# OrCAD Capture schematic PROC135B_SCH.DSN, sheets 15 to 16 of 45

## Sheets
15 15. SOC POWER: size C; title: SOC SUPPLY RAILS AND POWER SUPPLIES
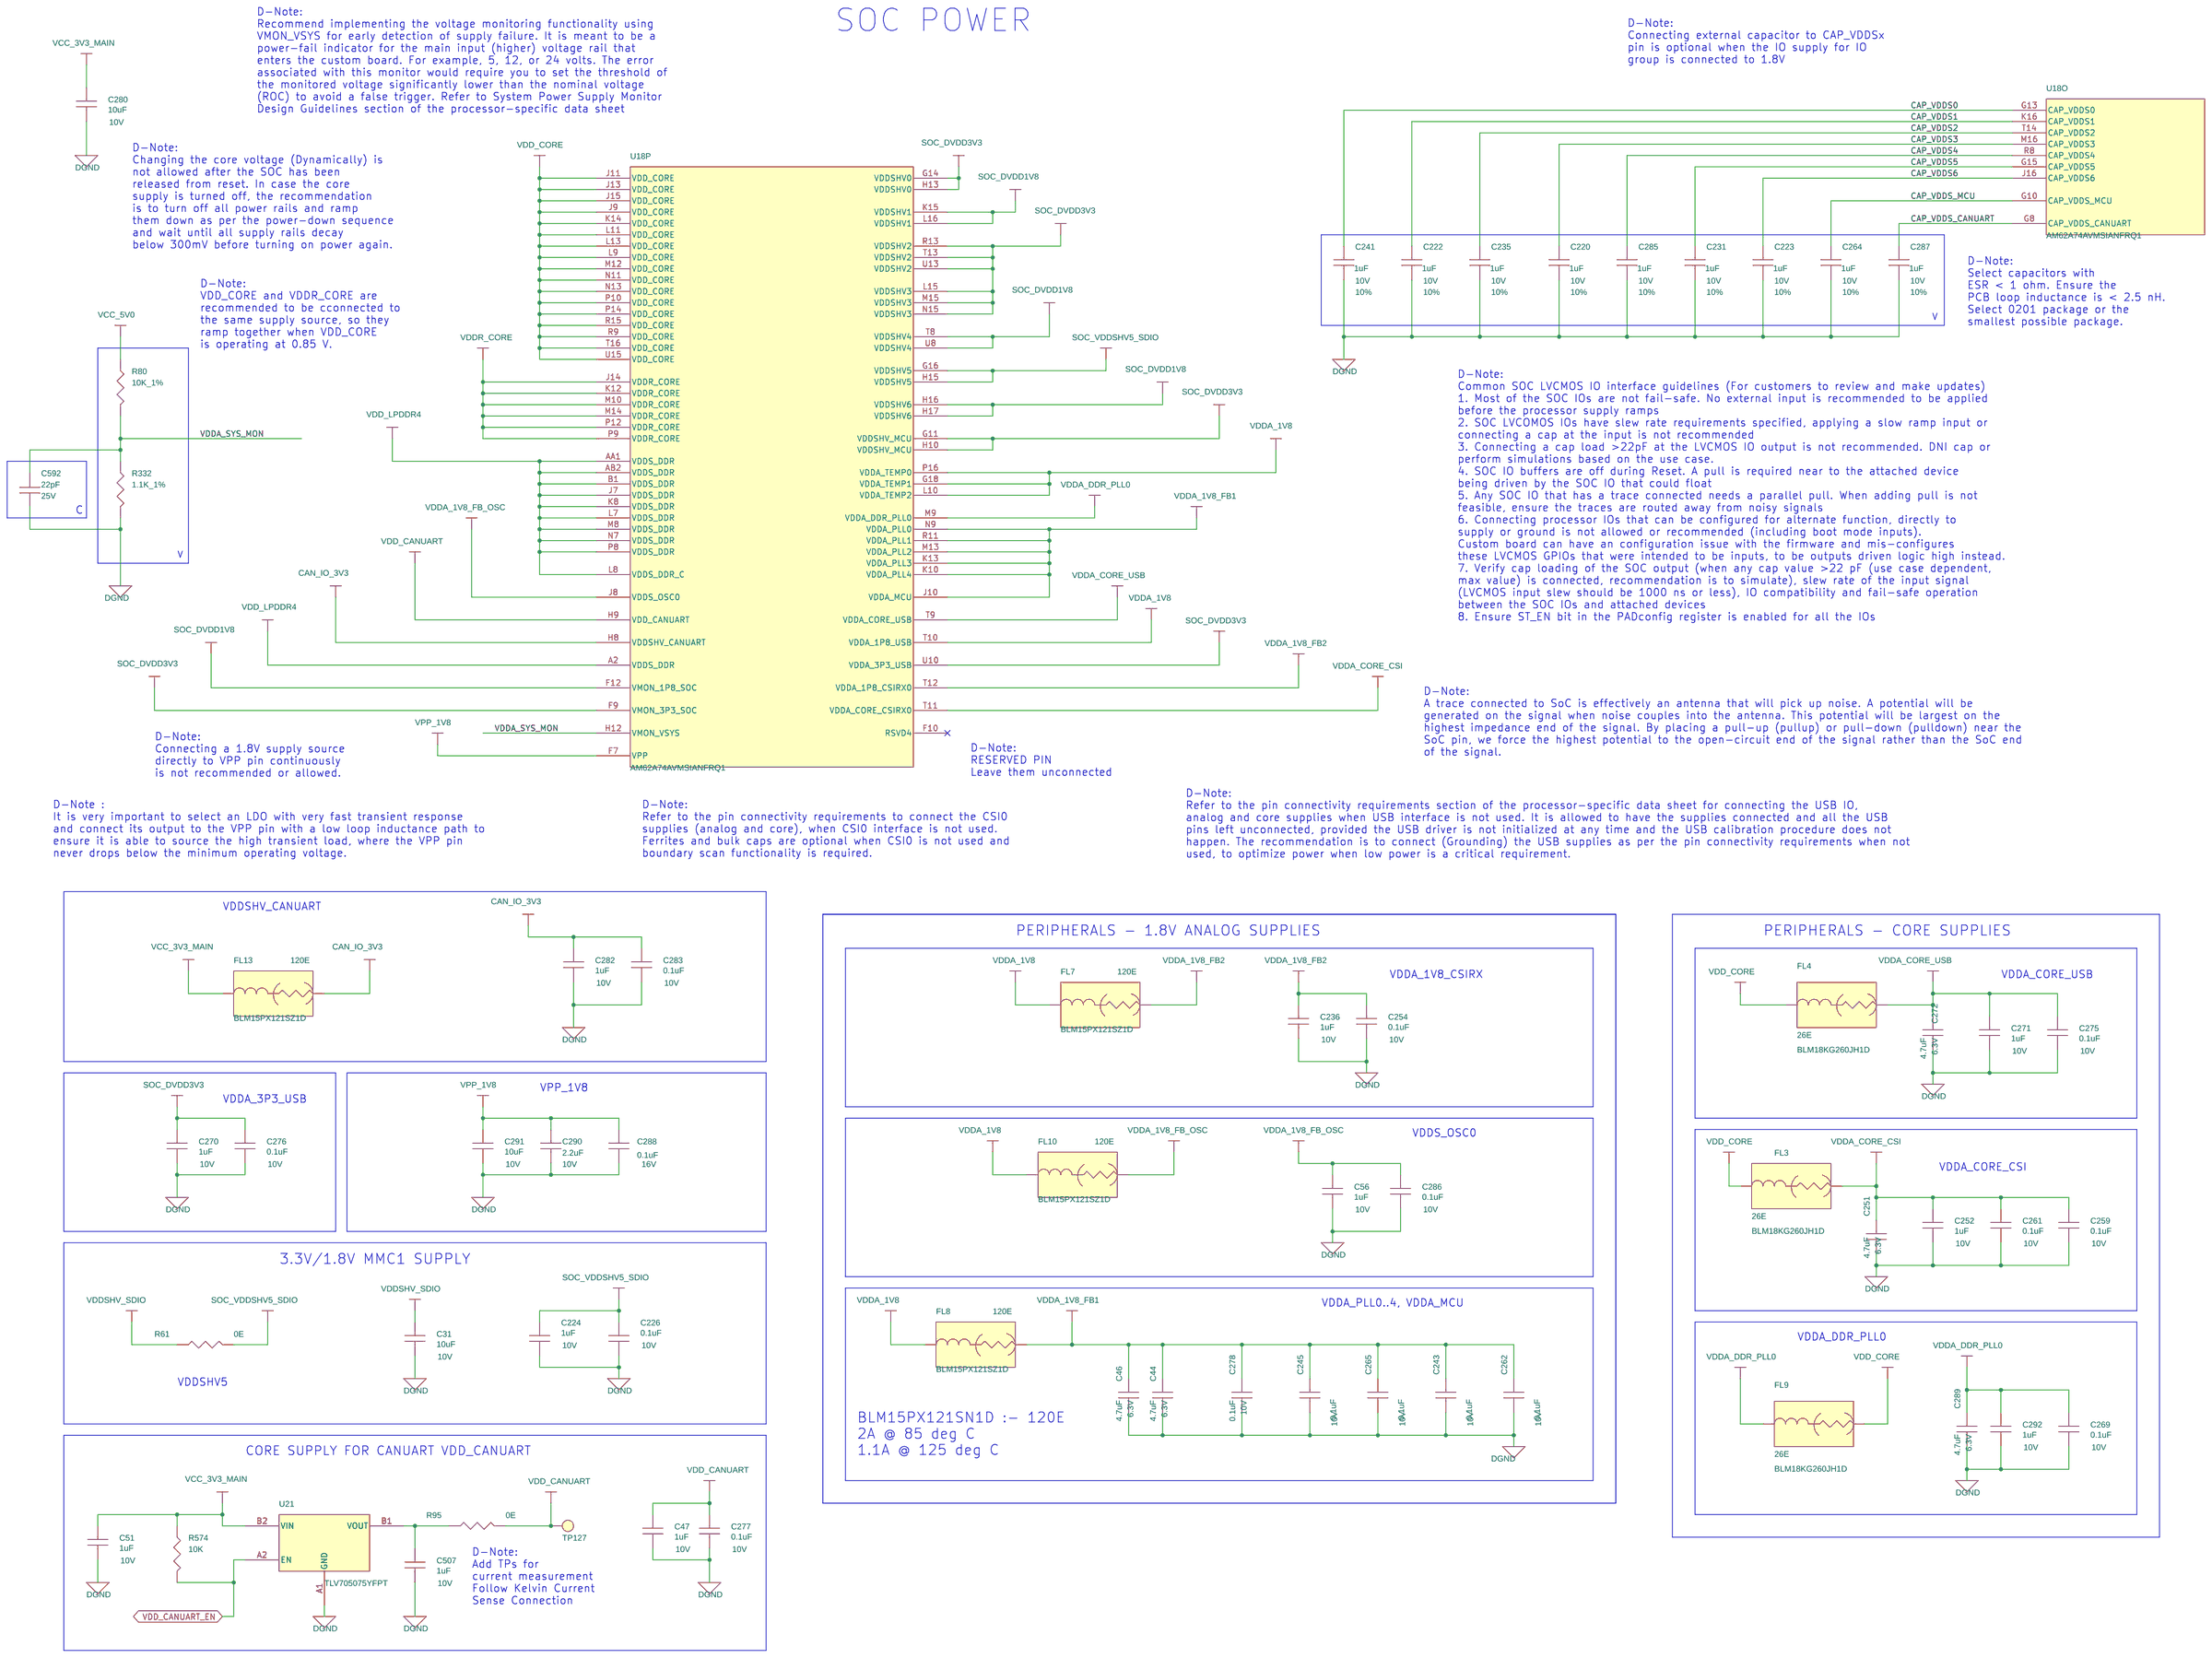
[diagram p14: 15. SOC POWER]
16 16. SOC POWER CAPS: size C; title: SOC POWER SUPPLIES - DECAPS & SOC GROUND VSS
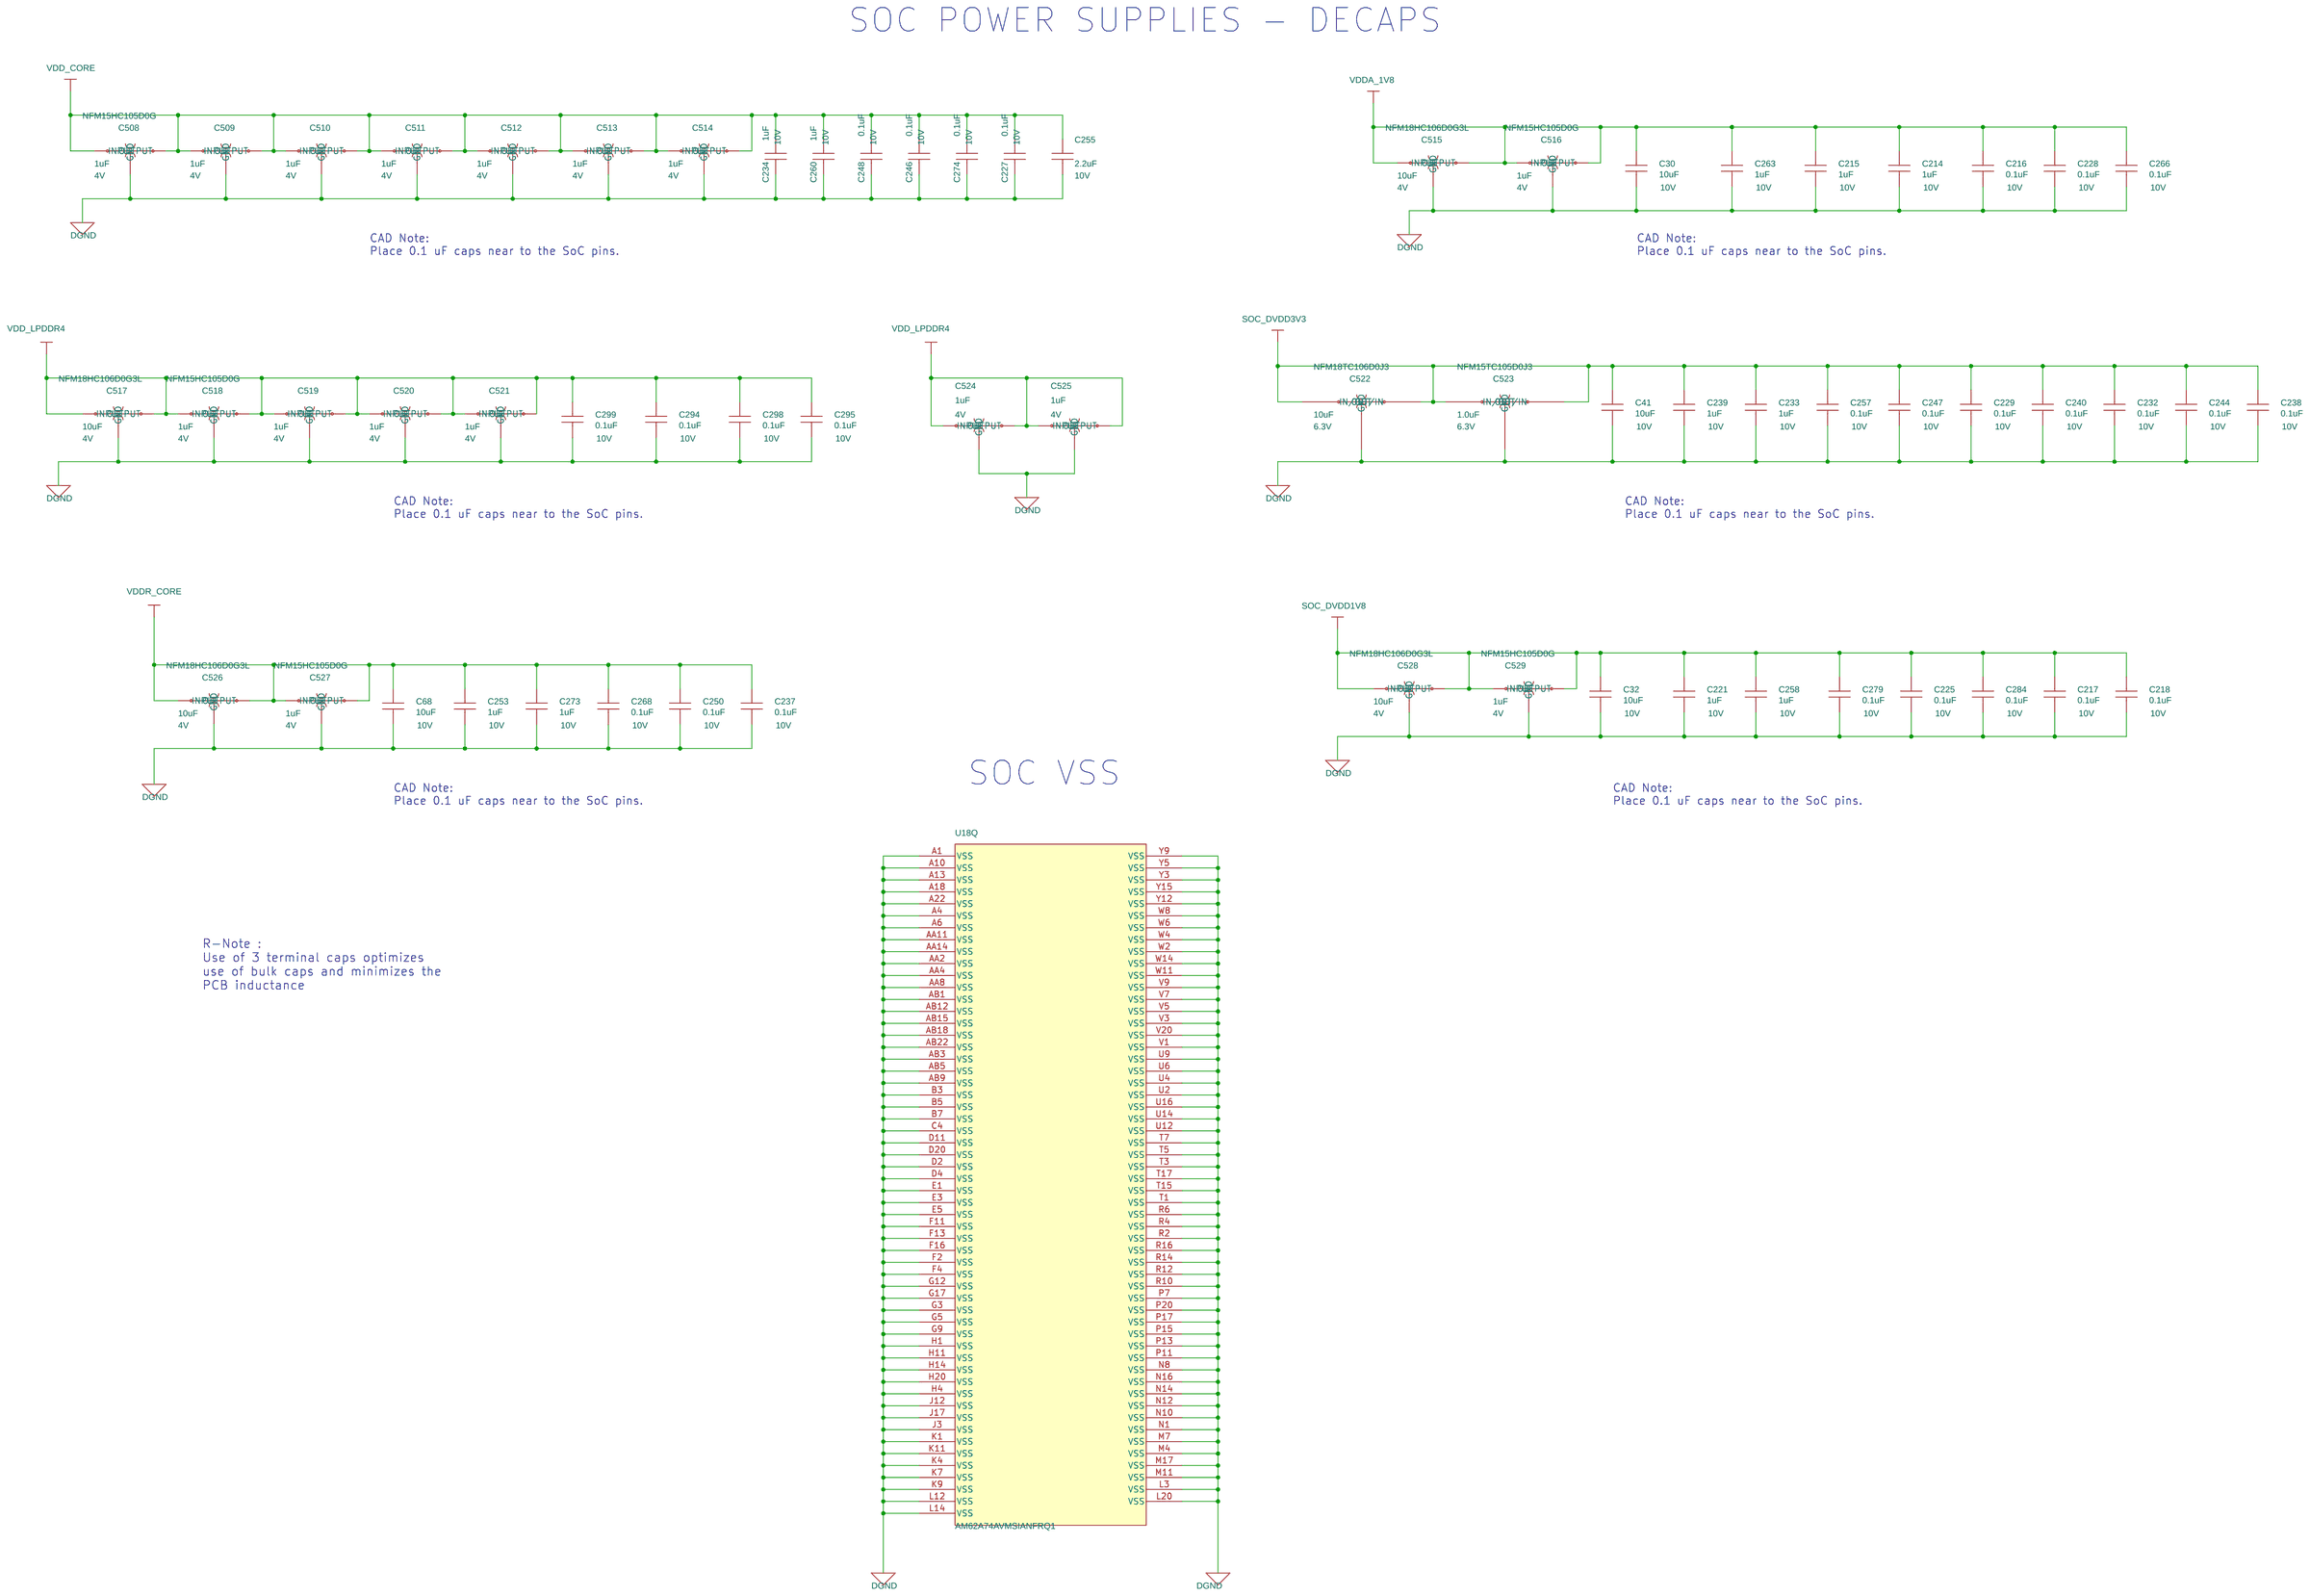
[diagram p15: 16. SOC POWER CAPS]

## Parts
sheet 15. SOC POWER
C31  10uF  [CAP0402_1]
C44  4.7uF  [CAP0201_0-5]
C46  4.7uF  [CAP0201_0-5]
C47  1uF  [CAP0201_0-5]
C51  1uF  [CAP0201_0-5]
C56  1uF  [CAP0201_0-5]
C220  1uF  [CAP0201_0-5]
C222  1uF  [CAP0201_0-5]
C223  1uF  [CAP0201_0-5]
C224  1uF  [CAP0201_0-5]
C226  0.1uF  [CAP0201_0-5]
C231  1uF  [CAP0201_0-5]
C235  1uF  [CAP0201_0-5]
C236  1uF  [CAP0201_0-5]
C241  1uF  [CAP0201_0-5]
C243  0.1uF  [CAP0201_0-5]
C245  0.1uF  [CAP0201_0-5]
C251  4.7uF  [CAP0201_0-5]
C252  1uF  [CAP0201_0-5]
C254  0.1uF  [CAP0201_0-5]
C259  0.1uF  [CAP0201_0-5]
C261  0.1uF  [CAP0201_0-5]
C262  0.1uF  [CAP0201_0-5]
C264  1uF  [CAP0201_0-5]
C265  0.1uF  [CAP0201_0-5]
C269  0.1uF  [CAP0201_0-5]
C270  1uF  [CAP0201_0-5]
C271  1uF  [CAP0201_0-5]
C272  4.7uF  [CAP0201_0-5]
C275  0.1uF  [CAP0201_0-5]
C276  0.1uF  [CAP0201_0-5]
C277  0.1uF  [CAP0201_0-5]
C278  0.1uF  [CAP0201_0-5]
C280  10uF  [CAP0402_1]
C282  1uF  [CAP0201_0-5]
C283  0.1uF  [CAP0201_0-5]
C285  1uF  [CAP0201_0-5]
C286  0.1uF  [CAP0201_0-5]
C287  1uF  [CAP0201_0-5]
C288  0.1uF  [CAP0201_0-5]
C289  4.7uF  [CAP0201_0-5]
C290  2.2uF  [CAP0201_0-75]
C291  10uF  [CAP0402_1]
C292  1uF  [CAP0201_0-5]
C507  1uF  [CAP0201_0-5]
C592  22pF  [CAP0201_0-5]
FL3  26E  [EMIFIL_BLM18P_0603_0-8]
FL4  26E  [EMIFIL_BLM18P_0603_0-8]
FL7  120E  [EMIFIL_BLM15A_0402_0-6]
FL8  120E  [EMIFIL_BLM15A_0402_0-6]
FL9  26E  [EMIFIL_BLM18P_0603_0-8]
FL10  120E  [EMIFIL_BLM15A_0402_0-6]
FL13  120E  [EMIFIL_BLM15A_0402_0-6]
R61  0E  [RES0402_0-5]
R80  10K_1%  [RES0402_0-5]
R95  0E  [RES0402_0-5]
R332  1.1K_1%  [RES0402_0-5]
R574  10K  [RES0201_0-5]
TP127  TP20_SMD  [TP20_SMD]
U21  TLV705075YFPT  [DSBGA4_15-74_30X30_0-5]
sheet 16. SOC POWER CAPS
C30  10uF  [CAP0402_1]
C32  10uF  [CAP0402_1]
C41  10uF  [CAP0402_1]
C68  10uF  [CAP0402_1]
C214  1uF  [CAP0201_0-5]
C215  1uF  [CAP0201_0-5]
C216  0.1uF  [CAP0201_0-5]
C217  0.1uF  [CAP0201_0-5]
C218  0.1uF  [CAP0201_0-5]
C221  1uF  [CAP0201_0-5]
C225  0.1uF  [CAP0201_0-5]
C227  0.1uF  [CAP0201_0-5]
C228  0.1uF  [CAP0201_0-5]
C229  0.1uF  [CAP0201_0-5]
C232  0.1uF  [CAP0201_0-5]
C233  1uF  [CAP0201_0-5]
C234  1uF  [CAP0201_0-5]
C237  0.1uF  [CAP0201_0-5]
C238  0.1uF  [CAP0201_0-5]
C239  1uF  [CAP0201_0-5]
C240  0.1uF  [CAP0201_0-5]
C244  0.1uF  [CAP0201_0-5]
C246  0.1uF  [CAP0201_0-5]
C247  0.1uF  [CAP0201_0-5]
C248  0.1uF  [CAP0201_0-5]
C250  0.1uF  [CAP0201_0-5]
C253  1uF  [CAP0201_0-5]
C255  2.2uF  [CAP0201_0-75]
C257  0.1uF  [CAP0201_0-5]
C258  1uF  [CAP0201_0-5]
C260  1uF  [CAP0201_0-5]
C263  1uF  [CAP0201_0-5]
C266  0.1uF  [CAP0201_0-5]
C268  0.1uF  [CAP0201_0-5]
C273  1uF  [CAP0201_0-5]
C274  0.1uF  [CAP0201_0-5]
C279  0.1uF  [CAP0201_0-5]
C284  0.1uF  [CAP0201_0-5]
C294  0.1uF  [CAP0201_0-5]
C295  0.1uF  [CAP0201_0-5]
C298  0.1uF  [CAP0201_0-5]
C299  0.1uF  [CAP0201_0-5]
C508  1uF  [EMIFIL_NFM15CC_0402_0-5]
C509  1uF  [EMIFIL_NFM15CC_0402_0-5]
C510  1uF  [EMIFIL_NFM15CC_0402_0-5]
C511  1uF  [EMIFIL_NFM15CC_0402_0-5]
C512  1uF  [EMIFIL_NFM15CC_0402_0-5]
C513  1uF  [EMIFIL_NFM15CC_0402_0-5]
C514  1uF  [EMIFIL_NFM15CC_0402_0-5]
C515  10uF  [EMIFIL_NFM18C_0603_0-7]
C516  1uF  [EMIFIL_NFM15CC_0402_0-5]
C517  10uF  [EMIFIL_NFM18C_0603_0-7]
C518  1uF  [EMIFIL_NFM15CC_0402_0-5]
C519  1uF  [EMIFIL_NFM15CC_0402_0-5]
C520  1uF  [EMIFIL_NFM15CC_0402_0-5]
C521  1uF  [EMIFIL_NFM15CC_0402_0-5]
C522  10uF  [EMIFIL_NFM18C_0603_1-4]
C523  1.0uF  [EMIFIL_NFM15CC_0402_0-5]
C524  1uF  [EMIFIL_NFM15CC_0402_0-5]
C525  1uF  [EMIFIL_NFM15CC_0402_0-5]
C526  10uF  [EMIFIL_NFM18C_0603_0-7]
C527  1uF  [EMIFIL_NFM15CC_0402_0-5]
C528  10uF  [EMIFIL_NFM18C_0603_0-7]
C529  1uF  [EMIFIL_NFM15CC_0402_0-5]
sheet 34. MCU HEADER
U18  AM62A74AVMSIANFRQ1  [FBGA484_31-49_710X710_2-7]  (sections A,B,C,D,E,F,G,H,I,J,K,L,M,N,O,P,Q)

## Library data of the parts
C30-C32 C41 C68 C280 C291 = CAP: CAP CERAMIC 10uF 10V 20% X5R 0402; Chkd/date: MANIRAJA/150219; Crtd /date: ALVY/150219; Custom_Duty: 15%; Customs_HS_Code: 85322990; Distributor_name: DIGIKEY; Distributor_part_number: 1276-6830-1-ND; Footprint Path: Y:\MIS_DATABASE\Library\ALTIUM_TOOL\PCB_FOOTPRINTS\Altium_Footprint_Lib.PcbLib; Height: 0.90MM; Library Path: Y:\MIS_DATABASE\Library\ALTIUM_TOOL\SCHEMATICS_PARTS\MS_DISCRETE_Library.schlib; Mfr_name: SAMSUNG; Mfr_part_number: CL05A106MP8NUB8; Mistral Part No: 120019020008-R; Package: 0402; Part_type: CAPACITORS\CERAMIC; Project: TI_60GHz-AOP; RoHS: RoHS; Temperature: -55°C+85°C; Tolerance: 20%; Voltage: 10V; Wattage: NA; Weight: NA; Datasheet: Y:\MIS_DATABASE\DATASHEETS\CAPACITORS\CL05A106MP8NUB8.PDF
C44 C46 C251 C272 C289 = CAP: CAP CERAMIC 4.7uF 6.3V 20% X5R 0201; Chkd/date: ALVY/020522; Crtd /date: TAMILARASU/020522; Custom_Duty: 15%; Customs_HS_Code: 85322990; Distributor_name: NA; Distributor_part_number: NA; Footprint Path: Y:\MIS_DATABASE\Library\ALTIUM_TOOL\PCB_FOOTPRINTS\Altium_Footprint_Lib.PcbLib; Height: 0.33MM; Library Path: Y:\MIS_DATABASE\Library\ALTIUM_TOOL\SCHEMATICS_PARTS\MS_DISCRETE_Library.schlib; Mfr_name: CAL-CHIP; Mfr_part_number: GMC02X5R475M6R3NT; Mistral Part No: 120022050001-R; Package: 0201; Part_type: CAPACITORS\CERAMIC; Project: TI_AM62A_SK_EVM; RoHS: RoHS; Temperature: -55°C+85°C; Tolerance: 20%; Voltage: 6.3V; Wattage: NA; Weight: NA; Datasheet: Y:\MIS_DATABASE\DATASHEETS\CAPACITORS\CALCHIP-GMC-SER.PDF
C47 C51 C56 C214 C215 C221 C224 C233 C234 C236 C239 C252 C253 C258 C260 C263 C270 C271 C273 C282 C292 C507 = CAP: CAP CERAMIC 1uF 10V 20% X5R 0201; Chkd/date: NAVEED/070415; Crtd /date: VASANTHA/230314; Custom_Duty: 15%; Customs_HS_Code: 85322990; Distributor_name: DIGIKEY; Distributor_part_number: 1276-1324-1-ND; Footprint Path: Y:\MIS_DATABASE\Library\ALTIUM_TOOL\PCB_FOOTPRINTS\Altium_Footprint_Lib.PcbLib; Height: 0.35MM; Library Path: Y:\MIS_DATABASE\Library\ALTIUM_TOOL\SCHEMATICS_PARTS\MS_DISCRETE_Library.schlib; Mfr_name: SAMSUNG; Mfr_part_number: CL03A105MP3NSNC; Mistral Part No: 120015030003-R; Package: 0201; Part_type: CAPACITORS\CERAMIC; Project: DUET BOARDS; RoHS: RoHS; Temperature: -55°C+85°C; Tolerance: 20%; Voltage: 10V; Wattage: NA; Weight: 0.17mg; Datasheet: Y:\MIS_DATABASE\DATASHEETS\CAPACITORS\CL03A105MP3NSNC.PDF
C220 C222 C223 C231 C235 C241 C264 C285 C287 = CAP: CAP CERAMIC 1uF 10V 10% X5R 0201; Alternate_mfr_name_A: MURATA; Alternate_mfr_part_number_A: GRM033R61C105ME15D; Chkd/date: MANIRAJA/130519; Crtd /date: ALVY/100519; Custom_Duty: 15%; Customs_HS_Code: 85322990; Distributor_name: DIGIKEY; Distributor_part_number: 1276-6795-1-ND; Footprint Path: Y:\MIS_DATABASE\Library\ALTIUM_TOOL\PCB_FOOTPRINTS\Altium_Footprint_Lib.PcbLib; Height: 0.35MM; Library Path: Y:\MIS_DATABASE\Library\ALTIUM_TOOL\SCHEMATICS_PARTS\MS_DISCRETE_Library.schlib; Mfr_name: SAMSUNG; Mfr_part_number: CL03A105KP3NSNC; Mistral Part No: 120019050005-R; Package: 0201; Part_type: CAPACITORS\CERAMIC; Project: BRUKER_SD820_COMMONDO; RoHS: RoHS; Temperature: -55°C+85°C; Tolerance: 10%; Voltage: 10V; Wattage: NA; Weight: NA; Datasheet: Y:\MIS_DATABASE\DATASHEETS\CAPACITORS\CL03A105KP3NSNC.PDF
C216-C218 C225-C229 C232 C237 C238 C240 C243-C248 C250 C254 C257 C259 C261 C262 C265 C266 C268 C269 C274-C279 C283 C284 C286 C294 C295 C298 C299 = CAP: CAP CERAMIC 0.1uF 10V 10% X5R 0201; Chkd/date: MANIRAJA/290421; Crtd /date: ALVY/290421; Custom_Duty: 15%; Customs_HS_Code: 85322990; Distributor_name: DIGIKEY; Distributor_part_number: 1276-1115-1-ND; Footprint Path: Y:\MIS_DATABASE\Library\ALTIUM_TOOL\PCB_FOOTPRINTS\Altium_Footprint_Lib.PcbLib; Height: 0.33MM; Library Path: Y:\MIS_DATABASE\Library\ALTIUM_TOOL\SCHEMATICS_PARTS\MS_DISCRETE_Library.schlib; Mfr_name: SAMSUNG; Mfr_part_number: CL03A104KP3NNNC; Mistral Part No: 120009050017-R; Package: 0201; Part_type: CAPACITORS\CERAMIC; Project: SRMS-SAR_BRD; RoHS: RoHS; Temperature: -55°C+85°C; Tolerance: 10%; Voltage: 10V; Wattage: NA; Weight: 0.33mg; Datasheet: Y:\MIS_DATABASE\DATASHEETS\CAPACITORS\CL03A104KP3NNNC.PDF
C288 = CAP: CAP CERAMIC 0.1uF 16V 10% X5R 0201; Chkd/date: PRADEEP/130623; Crtd /date: PRADEEP/130623; Custom_Duty: 15%; Customs_HS_Code: 85322990; Distributor_name: NA; Distributor_part_number: NA; Footprint Path: Y:\MIS_DATABASE\Library\ALTIUM_TOOL\PCB_FOOTPRINTS\Altium_Footprint_Lib.PcbLib; Height: 0.33MM; Library Path: Y:\MIS_DATABASE\Library\ALTIUM_TOOL\SCHEMATICS_PARTS\MS_DISCRETE_Library.schlib; Mfr_name: MURATA; Mfr_part_number: GRT033R61C104KE01; Mistral Part No: 120022060019-R; Package: 0201; Part_type: CAPACITORS\CERAMIC; Project: AM62P_SK; RoHS: RoHS; Temperature: -55°C+85°C; Tolerance: 10%; Voltage: 16V; Wattage: NA; Weight: 0.33mg; Datasheet: Y:\MIS_DATABASE\DATASHEETS\CAPACITORS\GRT033R61C104KE01XX.PDF
C255 C290 = CAP: CAP CERAMIC 2.2uF 10V 20% X5R 0201; Chkd/date: PRADEEP/130623; Crtd /date: PRADEEP/130623; Custom_Duty: 15%; Customs_HS_Code: 85322990; Distributor_name: NA; Distributor_part_number: NA; Footprint Path: Y:\MIS_DATABASE\Library\ALTIUM_TOOL\PCB_FOOTPRINTS\Altium_Footprint_Lib.PcbLib; Height: 0.55MM; Library Path: Y:\MIS_DATABASE\Library\ALTIUM_TOOL\SCHEMATICS_PARTS\MS_DISCRETE_Library.schlib; Mfr_name: MURATA; Mfr_part_number: GRM035R61A225ME01; Mistral Part No: 120022060026-R; Package: 0201; Part_type: CAPACITORS\CERAMIC; Project: AM62P_SK; RoHS: RoHS; Temperature: -55°C+85°C; Tolerance: 20%; Voltage: 10V; Wattage: NA; Weight: 0.57mg; Datasheet: Y:\MIS_DATABASE\DATASHEETS\CAPACITORS\GRM035R61A225ME01.PDF
C592 = CAP: CAP CERAMIC 22pF 25V 1% C0G(NP0) AUTO 0201; Chkd/date: MANIRAJA/311221; Crtd /date: ALVY/301221; Custom_Duty: 15%; Customs_HS_Code: 85322990; Distributor_name: MOUSER; Distributor_part_number: 81-GRT0335C1E220FA2D; Footprint Path: Y:\MIS_DATABASE\Library\ALTIUM_TOOL\PCB_FOOTPRINTS\Altium_Footprint_Lib.PcbLib; Height: 0.33MM; Library Path: Y:\MIS_DATABASE\Library\ALTIUM_TOOL\SCHEMATICS_PARTS\MS_DISCRETE_Library.schlib; Mfr_name: MURATA; Mfr_part_number: GRT0335C1E220FA02D; Mistral Part No: 120021120014-R; Package: 0201; Part_type: CAPACITORS\CERAMIC; Project: AM62Q_SKEVM_BRD; RoHS: RoHS; Temperature: -55°C+125°C; Tolerance: 1%; Voltage: 25V; Wattage: NA; Weight: 0.33mg; Datasheet: Y:\MIS_DATABASE\DATASHEETS\CAPACITORS\GRT0335C1E220FA02.PDF
FL3 FL4 FL9 = EMIFILTER_IND: IND FERRITE BEAD CHIP 26E 4A 0603; Chkd/date: ALVY/020522; Crtd /date: TAMILARASU/020522; Custom_Duty: 24%; Customs_HS_Code: 85437099; Distributor_name: DIGIKEY; Distributor_part_number: 490-14026-1-ND; Footprint Path: Y:\MIS_DATABASE\Library\ALTIUM_TOOL\PCB_FOOTPRINTS\Altium_Footprint_Lib.PcbLib; Height: 0.75MM; Library Path: Y:\MIS_DATABASE\Library\ALTIUM_TOOL\SCHEMATICS_PARTS\MS_FILTER_Library.schlib; Mfr_name: MURATA; Mfr_part_number: BLM18KG260JH1D; Mistral Part No: 130022050001-R; Package: 0603; Part_type: INDUCTOR; Project: TI_AM62A_SK_EVM; RoHS: RoHS; Temperature: -55°C+150°C; Tolerance: 25%; Voltage: NA; Wattage: NA; Weight: 4mg; Datasheet: Y:\MIS_DATABASE\DATASHEETS\DISCRETES\INDUCTORS\BLM18XX-B-J-H1D.PDF
FL7 FL8 FL10 FL13 = EMIFILTER_IND: IND FERRITE BEAD CHIP 120E 2A 0402; Crtd /date: SHANKARI/100425; Custom_Duty: 24%; Customs_HS_Code: 85369090; Distributor_name: DIGIKEY; Distributor_part_number: 490-16505-1-ND; Footprint Path: Y:\MIS_DATABASE\Library\ALTIUM_TOOL\PCB_FOOTPRINTS\Altium_Footprint_Lib.PcbLib; Height: 0.55MM; Library Path: Y:\MIS_DATABASE\Library\ALTIUM_TOOL\SCHEMATICS_PARTS\MS_FILTER_Library.schlib; Mfr_name: MURATA; Mfr_part_number: BLM15PX121SZ1D; Mistral Part No: 130025040021-R; Package: 0402; Part_type: INDUCTOR; Project: XWRL6844_EVM_PROTO; RoHS: RoHS; Temperature: -55°C+125°C; Tolerance: 25%; Voltage: NA; Wattage: NA; Weight: NA; Datasheet: Y:\MIS_DATABASE\DATASHEETS\DISCRETES\INDUCTORS\BLM15PX121SZ1D.PDF
R61 R95 = RESISTOR: RES 0E 1/10W JUMPER 0402; Chkd/date: VASANTHA/061216; Crtd /date: NAVEED/201014; Custom_Duty: 15%; Customs_HS_Code: 85332119; Distributor_name: DIGIKEY; Distributor_part_number: P0.0JCT-ND; Footprint Path: Y:\MIS_DATABASE\Library\ALTIUM_TOOL\PCB_FOOTPRINTS\Altium_Footprint_Lib.PcbLib; Height: 0.40MM; IBISSP_MODLES: VALUE REPEATING 2 TIME; Library Path: Y:\MIS_DATABASE\Library\ALTIUM_TOOL\SCHEMATICS_PARTS\MS_DISCRETE_Library.schlib; Mfr_name: PANASONIC-ECG; Mfr_part_number: ERJ-2GE0R00X; Mistral Part No: 110018030052-R; Package: 0402; Part_type: RESISTORS\FIXED; Project: AEGIS POM; RoHS: RoHS; Temperature: -55°C+155°C; Tolerance: NA; Voltage: NA; Wattage: 1/10W; Weight: 0.8mg; Datasheet: Y:\MIS_DATABASE\DATASHEETS\RESISTORS\PAN-ERJSER_NOV17.PDF
R80 = RESISTOR: RES 10K 1/10W 1% 0402; Chkd/date: MANIRAJA/190218; Crtd /date: NAVEED/280515; Custom_Duty: 15%; Customs_HS_Code: 85332119; Distributor_name: DIGIKEY; Distributor_part_number: P10.0KLCT-ND; Footprint Path: Y:\MIS_DATABASE\Library\ALTIUM_TOOL\PCB_FOOTPRINTS\Altium_Footprint_Lib.PcbLib; Height: 0.40MM; Library Path: Y:\MIS_DATABASE\Library\ALTIUM_TOOL\SCHEMATICS_PARTS\MS_DISCRETE_Library.schlib; Mfr_name: PANASONIC-ECG; Mfr_part_number: ERJ-2RKF1002X; Mistral Part No: 110015050015-R; Package: 0402; Part_type: RESISTORS\FIXED; Project: DLRL NARROW BAND; RoHS: RoHS; Temperature: -55°C+155°C; Tolerance: 1%; Voltage: NA; Wattage: 1/10W; Weight: 0.8mg; Datasheet: Y:\MIS_DATABASE\DATASHEETS\RESISTORS\PAN-ERJSER_NOV17.PDF
R332 = RESISTOR: RES 1.1K 1/16W 1% 0402; Chkd/date: MANIRAJA/081020; Crtd /date: ALVY/081020; Custom_Duty: 15%; Customs_HS_Code: 85332119; Distributor_name: DIGIKEY; Distributor_part_number: 541-1.10KLCT-ND; Footprint Path: Y:\MIS_DATABASE\Library\ALTIUM_TOOL\PCB_FOOTPRINTS\Altium_Footprint_Lib.PcbLib; Height: 0.40MM; Library Path: Y:\MIS_DATABASE\Library\ALTIUM_TOOL\SCHEMATICS_PARTS\MS_DISCRETE_Library.schlib; Mfr_name: VISHAY; Mfr_part_number: CRCW04021K10FKED; Mistral Part No: 110010120009-R; Package: 0402; Part_type: RESISTORS\FIXED; Project: VAGG_SBC_BRD; RoHS: RoHS; Temperature: -55°C+155°C; Tolerance: 1%; Voltage: NA; Wattage: 1/16W; Weight: 0.65mg; Datasheet: Y:\MIS_DATABASE\DATASHEETS\RESISTORS\CRCW0603.PDF
R574 = RESISTOR: RES 10K 1/20W 5% 0201; Chkd/date: MANIRAJA/050517; Crtd /date: MANIRAJA/050517; Custom_Duty: 15%; Customs_HS_Code: 85332119; Distributor_name: DIGIKEY; Distributor_part_number: 311-10KNCT-ND; Footprint Path: Y:\MIS_DATABASE\Library\ALTIUM_TOOL\PCB_FOOTPRINTS\Altium_Footprint_Lib.PcbLib; Height: 0.26MM; Library Path: Y:\MIS_DATABASE\Library\ALTIUM_TOOL\SCHEMATICS_PARTS\MS_DISCRETE_Library.schlib; Mfr_name: YAGEO AMERICA; Mfr_part_number: RC0201JR-0710KL; Mistral Part No: 110010070051-R; Package: 0201; Part_type: RESISTORS\FIXED; Project: GOLDEN-I LITE; RoHS: RoHS; Temperature: -55°C+125°C; Tolerance: 5%; Voltage: NA; Wattage: 1/20W; Weight: 0.17mg; Datasheet: Y:\MIS_DATABASE\DATASHEETS\RESISTORS\RCXXXXL-SER_MAR18.PDF
TP127 = TESTPOINT: TESTPOINT CIR 20 SMD; Chkd/date: SHREESHAIL/171006; Crtd /date: MAZHAR/171006; Custom_Duty: NA; Customs_HS_Code: NA; Distributor_name: NA; Distributor_part_number: NA; Footprint Path: Y:\MIS_DATABASE\Library\ALTIUM_TOOL\PCB_FOOTPRINTS\Altium_Footprint_Lib.PcbLib; Height: NA; Library Path: Y:\MIS_DATABASE\Library\ALTIUM_TOOL\SCHEMATICS_PARTS\MS_DISCRETE_Library.schlib; MECHANICAL 3D STEP FILE: NA; Mfr_name: LOCAL; Mistral Part No: NA; Package: SMD; Project: BT MODULE_CSRBC04; RoHS: NA; Temperature: NA; Tolerance: NA; Voltage: NA; Wattage: NA; Weight: NA; Datasheet: NA
U21 = TLV7050_DSBGA4: IC 200mA 0.75V LOW IQ LOW-DROPOUT REGULATOR DSBGA4; Chkd/date: ALVY/300522; Crtd /date: TAMILARASU/300522; Custom_Duty: 15%; Customs_HS_Code: 85423100; Distributor_name: DIGIKEY; Distributor_part_number: 296-TLV705075YFPTCT-ND; Footprint Path: Y:\MIS_DATABASE\Library\ALTIUM_TOOL\PCB_FOOTPRINTS\Altium_Footprint_Lib.PcbLib; Height: 0.50MM; Library Path: Y:\MIS_DATABASE\Library\ALTIUM_TOOL\SCHEMATICS_PARTS\MS_MISCPOWER_Library.schlib; Mfr_name: TEXAS INSTRUMENTS; Mistral Part No: 142022050034-R; Package: DSBGA4; Part_type: ICS\POWER\VOLTAGE REGULATOR; Project: TI_AM62A_SK_EVM; RoHS: RoHS; Temperature: -40°C+125°C; Tolerance: NA; Voltage: NA; Wattage: NA; Weight: 200mg; Datasheet: Y:\MIS_DATABASE\DATASHEETS\ICS\POWER\TLV705X.PDF
C508-C514 C516 C518-C521 C524 C525 C527 C529 = CAP_NFM: PASSIVE FILTER EMI 1uF 4V AUTO 0402; Chkd/date: MANIRAJA/251018; Crtd /date: ALVY/251018; Custom_Duty: 15%; Customs_HS_Code: 85412900; Distributor_name: NA; Distributor_part_number: NA; Footprint Path: Y:\MIS_DATABASE\Library\ALTIUM_TOOL\PCB_FOOTPRINTS\Altium_Footprint_Lib.PcbLib; Height: 0.50MM; Library Path: Y:\MIS_DATABASE\Library\ALTIUM_TOOL\SCHEMATICS_PARTS\MS_FILTER_Library.schlib; Mfr_name: MURATA; Mfr_part_number: NFM15HC105D0G; Mistral Part No: 130018100050; Package: 0402; Part_type: FILTER; Project: TI_J7ES_EVM_SOM; RoHS: NA; Temperature: NA; Tolerance: NA; Voltage: 4V; Wattage: NA; Weight: NA; Datasheet: Y:\MIS_DATABASE\DATASHEETS\DISCRETES\INDUCTORS\NFM15CC223C1A3.PDF
C515 C517 C526 C528 = CAP_NFM: PASSIVE FILTER EMI 10uF 4V 20% AUTO 0603; Chkd/date: PRAVEEN/080224; Crtd /date: TAMILARASU/080224; Custom_Duty: 0.15; Customs_HS_Code: 85412900; Distributor_name: DIGIKEY; Distributor_part_number: 490-NFM18HC106D0G3LCT-ND; Footprint Path: Y:\MIS_DATABASE\Library\ALTIUM_TOOL\PCB_FOOTPRINTS\Altium_Footprint_Lib.PcbLib; Height: 0.70MM; Library Path: Y:\MIS_DATABASE\Library\ALTIUM_TOOL\SCHEMATICS_PARTS\MS_FILTER_Library.schlib; Mfr_name: MURATA; Mfr_part_number: NFM18HC106D0G3L; Mistral Part No: 130024020005-R; Package: 0603; Part_type: FILTER; Project: AM62D_EVM; RoHS: NA; Temperature: -55°C+125°C; Tolerance: 20%; Voltage: 4V; Wattage: NA; Weight: NA; Datasheet: Y:\MIS_DATABASE\DATASHEETS\DISCRETES\INDUCTORS\NFM18HC106D0G3L.PDF
C522 = FILTER3_NFM18: PASSIVE FILTER EMI 10uF 6.3V 0603; Chkd/date: PRADEEP/130623; Crtd /date: PRADEEP/130623; Custom_Duty: 24%; Customs_HS_Code: 85439000; Distributor_name: NA; Distributor_part_number: NA; Footprint Path: Y:\MIS_DATABASE\Library\ALTIUM_TOOL\PCB_FOOTPRINTS\Altium_Footprint_Lib.PcbLib; Height: 1.35MM; Library Path: Y:\MIS_DATABASE\Library\ALTIUM_TOOL\SCHEMATICS_PARTS\MS_FILTER_Library.schlib; Mfr_name: MURATA; Mfr_part_number: NFM18TC106D0J3; Mistral Part No: 130023060021-R; Package: 0603; Part_type: FILTER; Project: AM62P_SK; RoHS: RoHS; Temperature: -55°C+125°C; Tolerance: NA; Voltage: 6.3V; Wattage: NA; Weight: NA; Datasheet: Y:\MIS_DATABASE\DATASHEETS\DISCRETES\INDUCTORS\NFM18TC106D0J3.PDF
C523 = FILTER3_NFM18: PASSIVE FILTER EMI 1.0uF 6.3V 0402; Chkd/date: PRADEEP/130623; Crtd /date: PRADEEP/130623; Custom_Duty: 24%; Customs_HS_Code: 85439000; Distributor_name: NA; Distributor_part_number: NA; Footprint Path: Y:\MIS_DATABASE\Library\ALTIUM_TOOL\PCB_FOOTPRINTS\Altium_Footprint_Lib.PcbLib; Height: 0.50MM; Library Path: Y:\MIS_DATABASE\Library\ALTIUM_TOOL\SCHEMATICS_PARTS\MS_FILTER_Library.schlib; Mfr_name: MURATA; Mfr_part_number: NFM15TC105D0J3; Mistral Part No: 130023060020-R; Package: 0402; Part_type: FILTER; Project: AM62P_SK; RoHS: RoHS; Temperature: -55°C+125°C; Tolerance: NA; Voltage: 6.3V; Wattage: NA; Weight: NA; Datasheet: Y:\MIS_DATABASE\DATASHEETS\DISCRETES\INDUCTORS\NFM15TC105D0J3.PDF
U18 = AM62A-EVM_SOC_FCBGA484: IC AM62A SK EVM SoC MICROPROCESSOR FCBGA484; Chkd/date: PRADEEP/120225; Crtd /date: SHANKARI/120225; Custom_Duty: 15%; Customs_HS_Code: 85369090; Distributor_name: NA; Distributor_part_number: NA; Footprint Path: Y:\MIS_DATABASE\Library\ALTIUM_TOOL\PCB_FOOTPRINTS\Altium_Footprint_Lib.PcbLib; Height: 2.65MM; Library Path: Y:\MIS_DATABASE\Library\ALTIUM_TOOL\SCHEMATICS_PARTS\MS_MICROPROCESSOR_Library.schlib; Library Ref: AM62A-EVM_SoC_FCBGA484; Mfr_name: TEXAS INSTRUMENTS; Mistral Part No: 141225020003-R; Package: FCBGA484; Part_type: ICS\DIGITAL\MICROPROCESSOR; Project: AM62A_SK_EVM; RoHS: NA; Temperature: NA; Tolerance: NA; Voltage: NA; Wattage: NA; Weight: NA; Datasheet: Y:\MIS_DATABASE\DATASHEETS\ICS\DIGITAL\MICROCONTROLLER\AM62A_SK_EVM.PDF

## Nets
DGND: C30.2 C31.2 C32.2 C41.2 C44.2 C46.2 C47.2 C51.2 C56.2 C68.2 C214.2 C215.2 C216.2 C217.2 C218.2 C220.2 C221.2 C222.2 C223.2 C224.2 C225.2 C226.2 C227.2 C228.2 C229.2 C231.2 C232.2 C233.2 C234.2 C235.2 C236.2 C237.2 C238.2 C239.2 C240.2 C241.2 C243.2 C244.2 C245.2 C246.2 C247.2 C248.2 C250.2 C251.2 C252.2 C253.2 C254.2 C255.2 C257.2 C258.2 C259.2 C260.2 C261.2 C262.2 C263.2 C264.2 C265.2 C266.2 C268.2 C269.2 C270.2 C271.2 C272.2 C273.2 C274.2 C275.2 C276.2 C277.2 C278.2 C279.2 C280.2 C282.2 C283.2 C284.2 C285.2 C286.2 C287.2 C288.2 C289.2 C290.2 C291.2 C292.2 C294.2 C295.2 C298.2 C299.2 C507.2 C508.2(GND) C509.2(GND) C510.2(GND) C511.2(GND) C512.2(GND) C513.2(GND) C514.2(GND) C515.2(GND) C516.2(GND) C517.2(GND) C518.2(GND) C519.2(GND) C520.2(GND) C521.2(GND) C522.2(GND) C523.2(GND) C524.2(GND) C525.2(GND) C526.2(GND) C527.2(GND) C528.2(GND) C529.2(GND) C592.1 R332.2 U18.A1(VSS) U18.A4(VSS) U18.A6(VSS) U18.A10(VSS) U18.A13(VSS) U18.A18(VSS) U18.A22(VSS) U18.AA2(VSS) U18.AA4(VSS) U18.AA8(VSS) U18.AA11(VSS) U18.AA14(VSS) U18.AB1(VSS) U18.AB3(VSS) U18.AB5(VSS) U18.AB9(VSS) U18.AB12(VSS) U18.AB15(VSS) U18.AB18(VSS) U18.AB22(VSS) U18.B3(VSS) U18.B5(VSS) U18.B7(VSS) U18.C4(VSS) U18.D2(VSS) U18.D4(VSS) U18.D11(VSS) U18.D20(VSS) U18.E1(VSS) U18.E3(VSS) U18.E5(VSS) U18.F2(VSS) U18.F4(VSS) U18.F11(VSS) U18.F13(VSS) U18.F16(VSS) U18.G3(VSS) U18.G5(VSS) U18.G9(VSS) U18.G12(VSS) U18.G17(VSS) U18.H1(VSS) U18.H4(VSS) U18.H11(VSS) U18.H14(VSS) U18.H20(VSS) U18.J3(VSS) U18.J12(VSS) U18.J17(VSS) U18.K1(VSS) U18.K4(VSS) U18.K7(VSS) U18.K9(VSS) U18.K11(VSS) U18.L3(VSS) U18.L12(VSS) U18.L14(VSS) U18.L20(VSS) U18.M4(VSS) U18.M7(VSS) U18.M11(VSS) U18.M17(VSS) U18.N1(VSS) U18.N8(VSS) U18.N10(VSS) U18.N12(VSS) U18.N14(VSS) U18.N16(VSS) U18.P7(VSS) U18.P11(VSS) U18.P13(VSS) U18.P15(VSS) U18.P17(VSS) U18.P20(VSS) U18.R2(VSS) U18.R4(VSS) U18.R6(VSS) U18.R10(VSS) U18.R12(VSS) U18.R14(VSS) U18.R16(VSS) U18.T1(VSS) U18.T3(VSS) U18.T5(VSS) U18.T7(VSS) U18.T15(VSS) U18.T17(VSS) U18.U2(VSS) U18.U4(VSS) U18.U6(VSS) U18.U9(VSS) U18.U12(VSS) U18.U14(VSS) U18.U16(VSS) U18.V1(VSS) U18.V3(VSS) U18.V5(VSS) U18.V7(VSS) U18.V9(VSS) U18.V20(VSS) U18.W2(VSS) U18.W4(VSS) U18.W6(VSS) U18.W8(VSS) U18.W11(VSS) U18.W14(VSS) U18.Y3(VSS) U18.Y5(VSS) U18.Y9(VSS) U18.Y12(VSS) U18.Y15(VSS) U21.A1(GND) ; also on sheet 10 11 12 13 14 17 18 19 20 21 22 23 24 25 26 27 28 29 30 31 32 33 34 35 36 37 38 39 40 41 42 43 44
VCC_3V3_MAIN: C51.1 C280.1 FL13.1 R574.1 U21.B2(VIN) ; also on sheet 12 13 26
VCC_5V0: R80.1 ; also on sheet 10 11 33 35 38 41
VDD_CANUART: C47.1 C277.1 R95.2 TP127.1(TP) U18.H9(VDD_CANUART)
VDD_CANUART_EN: R574.2 U21.A2(EN) ; also on sheet 13
VDD_CORE: C227.1 C234.1 C246.1 C248.1 C255.1 C260.1 C274.1 C508.1(INPUT) C508.3(OUTPUT) C509.1(INPUT) C509.3(OUTPUT) C510.1(INPUT) C510.3(OUTPUT) C511.1(INPUT) C511.3(OUTPUT) C512.1(INPUT) C512.3(OUTPUT) C513.1(INPUT) C513.3(OUTPUT) C514.1(INPUT) C514.3(OUTPUT) FL3.1 FL4.1 FL9.2 U18.J9(VDD_CORE) U18.J11(VDD_CORE) U18.J13(VDD_CORE) U18.J15(VDD_CORE) U18.K14(VDD_CORE) U18.L9(VDD_CORE) U18.L11(VDD_CORE) U18.L13(VDD_CORE) U18.M12(VDD_CORE) U18.N11(VDD_CORE) U18.N13(VDD_CORE) U18.P10(VDD_CORE) U18.P14(VDD_CORE) U18.R9(VDD_CORE) U18.R15(VDD_CORE) U18.T16(VDD_CORE) U18.U15(VDD_CORE) ; also on sheet 13
VDD_LPDDR4: C294.1 C295.1 C298.1 C299.1 C517.1(INPUT) C517.3(OUTPUT) C518.1(INPUT) C518.3(OUTPUT) C519.1(INPUT) C519.3(OUTPUT) C520.1(INPUT) C520.3(OUTPUT) C521.1(INPUT) C521.3(OUTPUT) C524.1(INPUT) C524.3(OUTPUT) C525.1(INPUT) C525.3(OUTPUT) U18.A2(VDDS_DDR) U18.AA1(VDDS_DDR) U18.AB2(VDDS_DDR) U18.B1(VDDS_DDR) U18.J7(VDDS_DDR) U18.K8(VDDS_DDR) U18.L7(VDDS_DDR) U18.L8(VDDS_DDR_C) U18.M8(VDDS_DDR) U18.N7(VDDS_DDR) U18.P8(VDDS_DDR) ; also on sheet 13 17
VDDA_1V8: C30.1 C214.1 C215.1 C216.1 C228.1 C263.1 C266.1 C515.1(INPUT) C515.3(OUTPUT) C516.1(INPUT) C516.3(OUTPUT) FL7.1 FL8.1 FL10.1 U18.G18(VDDA_TEMP1) U18.L10(VDDA_TEMP2) U18.P16(VDDA_TEMP0) U18.T10(VDDA_1P8_USB) ; also on sheet 13 25
VDDA_1V8_FB1: C44.1 C46.1 C243.1 C245.1 C262.1 C265.1 C278.1 FL8.2 U18.J10(VDDA_MCU) U18.K10(VDDA_PLL4) U18.K13(VDDA_PLL3) U18.M13(VDDA_PLL2) U18.N9(VDDA_PLL0) U18.R11(VDDA_PLL1)
VDDA_1V8_FB2: C236.1 C254.1 FL7.2 U18.T12(VDDA_1P8_CSIRX0)
VDDA_1V8_FB_OSC: C56.1 C286.1 FL10.2 U18.J8(VDDS_OSC0)
VDDA_DDR_PLL0: C269.1 C289.1 C292.1 FL9.1 U18.M9(VDDA_DDR_PLL0)
VDDA_SYS_MON: C592.2 R80.2 R332.1 U18.H12(VMON_VSYS)
VDDR_CORE: C68.1 C237.1 C250.1 C253.1 C268.1 C273.1 C526.1(INPUT) C526.3(OUTPUT) C527.1(INPUT) C527.3(OUTPUT) U18.J14(VDDR_CORE) U18.K12(VDDR_CORE) U18.M10(VDDR_CORE) U18.M14(VDDR_CORE) U18.P9(VDDR_CORE) U18.P12(VDDR_CORE) ; also on sheet 13 36
VDDSHV_SDIO: C31.1 R61.1 ; also on sheet 20
 VDDA_CORE_CSI: C251.1 C252.1 C259.1 C261.1 FL3.2 U18.T11(VDDA_CORE_CSIRX0)
 VDDA_CORE_USB: C271.1 C272.1 C275.1 FL4.2 U18.T9(VDDA_CORE_USB)
CAN_IO_3V3: C282.1 C283.1 FL13.2 U18.H8(VDDSHV_CANUART) ; also on sheet 13 31 34 44
CAP_VDDS0: C241.1 U18.G13(CAP_VDDS0)
CAP_VDDS1: C222.1 U18.K16(CAP_VDDS1)
CAP_VDDS2: C235.1 U18.T14(CAP_VDDS2)
CAP_VDDS3: C220.1 U18.M16(CAP_VDDS3)
CAP_VDDS4: C285.1 U18.R8(CAP_VDDS4)
CAP_VDDS5: C231.1 U18.G15(CAP_VDDS5)
CAP_VDDS6: C223.1 U18.J16(CAP_VDDS6)
CAP_VDDS_CANUART: C287.1 U18.G8(CAP_VDDS_CANUART)
CAP_VDDS_MCU: C264.1 U18.G10(CAP_VDDS_MCU)
SOC_DVDD1V8: C32.1 C217.1 C218.1 C221.1 C225.1 C258.1 C279.1 C284.1 C528.1(INPUT) C528.3(OUTPUT) C529.1(INPUT) C529.3(OUTPUT) U18.F12(VMON_1P8_SOC) U18.H16(VDDSHV6) U18.H17(VDDSHV6) U18.K15(VDDSHV1) U18.L16(VDDSHV1) U18.T8(VDDSHV4) U18.U8(VDDSHV4) ; also on sheet 13 17
SoC_DVDD3V3: C41.1 C229.1 C232.1 C233.1 C238.1 C239.1 C240.1 C244.1 C247.1 C257.1 C270.1 C276.1 C522.1(IN/OUT) C522.3(OUT/IN) C523.1(IN/OUT) C523.3(OUT/IN) U18.F9(VMON_3P3_SOC) U18.G11(VDDSHV_MCU) U18.G14(VDDSHV0) U18.H10(VDDSHV_MCU) U18.H13(VDDSHV0) U18.L15(VDDSHV3) U18.M15(VDDSHV3) U18.N15(VDDSHV3) U18.R13(VDDSHV2) U18.T13(VDDSHV2) U18.U10(VDDA_3P3_USB) U18.U13(VDDSHV2) ; also on sheet 13
SoC_VDDSHV5_SDIO: C224.1 C226.1 R61.2 U18.G16(VDDSHV5) U18.H15(VDDSHV5)
VPP_1V8: C288.1 C290.1 C291.1 U18.F7(VPP) ; also on sheet 13
N23233575: C507.1 R95.1 U21.B1(VOUT)

Not connected (* = marked no-connect by the designer): U18 F10(RSVD4)*

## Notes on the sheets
sheet 15
- D-Note:
  Recommend implementing the voltage monitoring functionality using
  VMON_VSYS for early detection of supply failure. It is meant to be a
  power-fail indicator for the main input (higher) voltage rail that
  enters the custom board. For example, 5, 12, or 24 volts. The error
  associated with this monitor would require you to set the threshold of
  the monitored voltage significantly lower than the nominal voltage
  (ROC) to avoid a false trigger. Refer to System Power Supply Monitor
  Design Guidelines section of the processor-specific data sheet
- SOC POWER
- D-Note:
  Connecting external capacitor to CAP_VDDSx
  pin is optional when the IO supply for IO
  group is connected to 1.8V
- D-Note:
  Changing the core voltage (Dynamically) is
  not allowed after the SOC has been
  released from reset. In case the core
  supply is turned off, the recommendation
  is to turn off all power rails and ramp
  them down as per the power-down sequence
  and wait until all supply rails decay
  below 300mV before turning on power again.
- D-Note:
  Select capacitors with
  ESR < 1 ohm. Ensure the
  PCB loop inductance is < 2.5 nH.
  Select 0201 package or the
  smallest possible package.
- D-Note:
  VDD_CORE and VDDR_CORE are
  recommended to be cconnected to
  the same supply source, so they
  ramp together when VDD_CORE
  is operating at 0.85 V.
- V
- D-Note:
  Common SOC LVCMOS IO interface guidelines (For customers to review and make updates)
  1. Most of the SOC IOs are not fail-safe. No external input is recommended to be applied
  before the processor supply ramps
  2. SOC LVCOMOS IOs have slew rate requirements specified, applying a slow ramp input or
  connecting a cap at the input is not recommended
  3. Connecting a cap load >22pF at the LVCMOS IO output is not recommended. DNI cap or
  perform simulations based on the use case.
  4. SOC IO buffers are off during Reset. A pull is required near to the attached device
  being driven by the SOC IO that could float
  5. Any SOC IO that has a trace connected needs a parallel pull. When adding pull is not
  feasible, ensure the traces are routed away from noisy signals
  6. Connecting processor IOs that can be configured for alternate function, directly to
  supply or ground is not allowed or recommended (including boot mode inputs).
  Custom board can have an configuration issue with the firmware and mis-configures
  these LVCMOS GPIOs that were intended to be inputs, to be outputs driven logic high instead.
  7. Verify cap loading of the SOC output (when any cap value >22 pF (use case dependent,
  max value) is connected, recommendation is to simulate), slew rate of the input signal
  (LVCMOS input slew should be 1000 ns or less), IO compatibility and fail-safe operation
  between the SOC IOs and attached devices
  8. Ensure ST_EN bit in the PADconfig register is enabled for all the IOs
- C
- V
- D-Note:
  A trace connected to SoC is effectively an antenna that will pick up noise. A potential will be
  generated on the signal when noise couples into the antenna. This potential will be largest on the
  highest impedance end of the signal. By placing a pull-up (pullup) or pull-down (pulldown) near the
  SoC pin, we force the highest potential to the open-circuit end of the signal rather than the SoC end
  of the signal.
- D-Note:
  Connecting a 1.8V supply source
  directly to VPP pin continuously
  is not recommended or allowed.
- D-Note:
  RESERVED PIN
  Leave them unconnected
- D-Note :
  It is very important to select an LDO with very fast transient response
  and connect its output to the VPP pin with a low loop inductance path to
  ensure it is able to source the high transient load, where the VPP pin
  never drops below the minimum operating voltage.
- D-Note:
  Refer to the pin connectivity requirements to connect the CSI0
  supplies (analog and core), when CSI0 interface is not used.
  Ferrites and bulk caps are optional when CSI0 is not used and
  boundary scan functionality is required.
- D-Note:
  Refer to the pin connectivity requirements section of the processor-specific data sheet for connecting the USB IO,
  analog and core supplies when USB interface is not used. It is allowed to have the supplies connected and all the USB
  pins left unconnected, provided the USB driver is not initialized at any time and the USB calibration procedure does not
  happen. The recommendation is to connect (Grounding) the USB supplies as per the pin connectivity requirements when not
  used, to optimize power when low power is a critical requirement.
- VDDSHV_CANUART
- PERIPHERALS - 1.8V ANALOG SUPPLIES
- PERIPHERALS - CORE SUPPLIES
- VDDA_1V8_CSIRX
- VDDA_CORE_USB
- VDDA_3P3_USB
- VPP_1V8
- VDDS_OSC0
- VDDA_CORE_CSI
- 3.3V/1.8V MMC1 SUPPLY
- VDDA_PLL0..4, VDDA_MCU
- VDDA_DDR_PLL0
- VDDSHV5
- BLM15PX121SN1D :- 120E
  2A @ 85 deg C
  1.1A @ 125 deg C
- CORE SUPPLY FOR CANUART VDD_CANUART
- D-Note:
  Add TPs for
  current measurement
  Follow Kelvin Current
  Sense Connection
sheet 16
- SOC POWER SUPPLIES - DECAPS
- CAD Note:
  Place 0.1 uF caps near to the SoC pins.
- CAD Note:
  Place 0.1 uF caps near to the SoC pins.
- CAD Note:
  Place 0.1 uF caps near to the SoC pins.
- CAD Note:
  Place 0.1 uF caps near to the SoC pins.
- SOC VSS
- CAD Note:
  Place 0.1 uF caps near to the SoC pins.
- CAD Note:
  Place 0.1 uF caps near to the SoC pins.
- R-Note :
  Use of 3 terminal caps optimizes
  use of bulk caps and minimizes the
  PCB inductance
